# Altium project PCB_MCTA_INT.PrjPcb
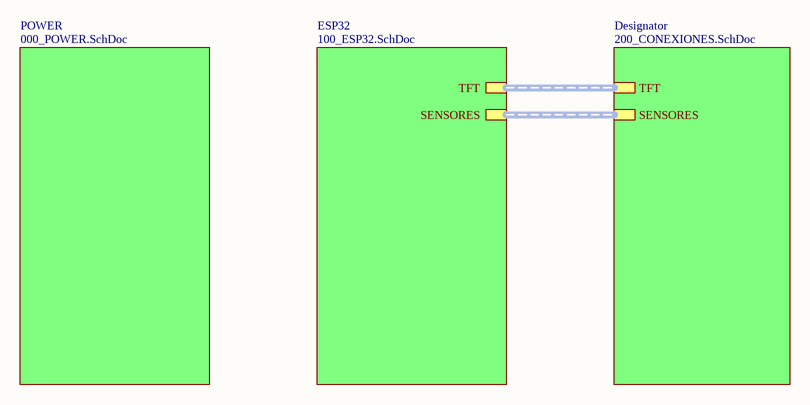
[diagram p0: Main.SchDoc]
4 sheets, 33 parts. Net scope: hierarchical (ports join the sheet entries above them; power ports are global).
Board file: PCB_MACETA.PcbDoc
Sheets:
  Main.SchDoc
    POWER = 000_POWER.SchDoc
    ESP32 = 100_ESP32.SchDoc
    Designator = 200_CONEXIONES.SchDoc

## Sheet Main.SchDoc: Maceta_Inteligente
size A4; DrawnBy: Alexis Andres Valencia; Revision: V1R1; SheetNumber: 1; SheetTotal: 4

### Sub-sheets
Designator = 200_CONEXIONES.SchDoc: TFT (harness TFT_HARNESS), SENSORES (harness SESORES_HARNESS)
ESP32 = 100_ESP32.SchDoc: TFT (harness TFT_HARNESS), SENSORES (harness SESORES_HARNESS)
POWER = 000_POWER.SchDoc: no entries

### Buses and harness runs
harness sheet Designator/SENSORES = sheet ESP32/SENSORES
harness sheet Designator/TFT = sheet ESP32/TFT

## Sheet 000_POWER.SchDoc: MACETA INTELIGENTE
size A4; DrawnBy: ALEXIS VALENCIA; SheetNumber: 2; SheetTotal: 4
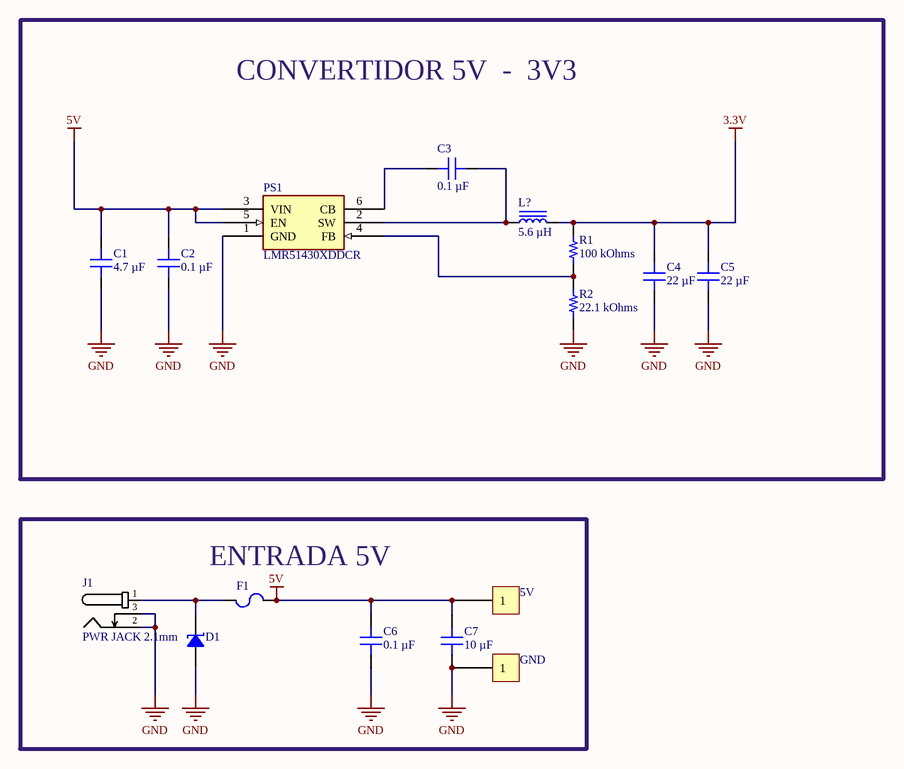
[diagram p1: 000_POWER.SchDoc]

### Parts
C1  4.7 µF  [CAP 0603_1608]
C2  0.1 µF  [CAP 0603_1608]
C3  0.1 µF  [CAP 0603_1608]
C4  22 µF  [CAP 0603_1608]
C5  22 µF  [CAP 0603_1608]
C6  0.1 µF  [CAP 0603_1608]
C7  10 µF  [CAP 0603_1608]
D1  SMAJ5.0A  [DO214AC SMA]  (value not drawn)
F1  MFU1206FF05000P100  [FUSE 1206_3216 0.6MM]  (value not drawn)
J1  PWR JACK 2.1mm  [CON_POWER_BARREL_2.1MM_3CONN]
L1  5.6 µH  [WURTH WE-PD 1280]
PS1  LMR51430XDDCR  [SOT95P280X110-6N]
R1  100 kOhms  [RES 0603_1608]
R2  22.1 kOhms  [RES 0603_1608]
TP1  5V  [Pad_SMD]
TP2  GND  [Pad_SMD]

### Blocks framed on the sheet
CONVERTIDOR 5V  -  3V3: C1-C5 L1 PS1 R1 R2
ENTRADA 5V: C6 C7 D1 F1 J1 TP1 TP2

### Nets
3.3V: C4.2 C5.2 L1.2 R1.2
5V: C1.2 C2.2 C6.2 C7.2 F1.2 PS1.3(VIN) PS1.5(EN) TP1.TP?(1)
GND: C1.1 C2.1 C4.1 C5.1 C6.1 C7.1 D1.1 J1.2 J1.3 PS1.1(GND) R2.1 TP2.TP?(1)
NetC3_1: C3.1 L1.1 PS1.2(SW)
NetC3_2: C3.2 PS1.6(CB)
NetD1_2: D1.2 F1.1 J1.1
NetPS1_4: PS1.4(FB) R1.1 R2.2

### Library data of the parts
C1 = 06033D475KAT2A: CAP CER 4.7UF 25V X5R 0603; manufacturer: KYOCERA AVX; Tolerance: ±10%
C2 C3 C6 = CL10E104KC8VPNC: CAP CER 100NF 100V X8L 0603; manufacturer: Samsung Electro-Mechanics; Tolerance: ±10%
C4 C5 = 0603YD226MAT2A: CAP CER 22UF 16V X5R 0603; manufacturer: KYOCERA AVX; Tolerance: ±20%
C7 = 0603X106M100CT: CAP CER 10UF 10V X5R 0603; manufacturer: Walsin Technology Corporation; Tolerance: ±20%
D1 = SMAJ5.0A: TVS DIODE 5VWM 9.2VC DO214AC; Manufacturer: Littelfuse Inc.; Current - Peak Pulse (10/1000µs): 43.5A; Power Line Protection: No; Power - Peak Pulse: 400W; Type: Zener; Unidirectional Channels: 1; Voltage - Breakdown (Min): 6.4V; Voltage - Clamping (Max) @ Ipp: 9.2V; Voltage - Reverse Standoff (Typ): 5V
F1 = MFU1206FF05000P100: FUSE BOARD MOUNT 5A 63VDC 1206; Manufacturer: Vishay Beyschlag; Approval Agency: UL; Breaking Capacity @ Rated Voltage: 50A; Fuse Type: Board Mount (Cartridge Style Excluded); Melting I²t: 0.2275; Response Time: Fast Blow; Voltage Rating - DC: 63V
J1 = Con_Power_Jack_2.1mm_3pins: CONN PWR JACK 2X5.5MM SOLDER; Manufacturer: HCTL; Manufacturer Part Number: HC-DC-005-2.0T
L1 = 74477005: FIXED IND 5.6UH 8A 17 MOHM SMD; Manufacturer: Würth Elektronik; Current - Saturation: 8.2A; DC Resistance (DCR): 17mOhm Max; Frequency - Self Resonant: 24MHz; Inductance Frequency - Test: 1 kHz; Material - Core: Ferrite; Shielding: Shielded; Tolerance: -20%, +40%; Type: Drum Core, Wirewound
PS1 = LMR51430XDDCR: Power Supply; Manufacturer_Name: Texas Instruments
R1 = AA0603FR-07100KL: RES SMD 100K OHM 1% 1/10W 0603; Manufacturer: Yageo; Power (Watts): 0.1W, 1/10W; Temperature Coefficient: ±150ppm/°C
R2 = AC0603FR-0722K1L: RES SMD 22.1K OHM 1% 1/10W 0603; Manufacturer: Yageo; Power (Watts): 0.1W, 1/10W; Temperature Coefficient: ±100ppm/°C
TP1 TP2 = Test: Test1.5mm

## Sheet 100_ESP32.SchDoc: MACETA INTELIGENTE
size A4; DrawnBy: ALEXIS VALENCIA; SheetNumber: 3; SheetTotal: 4
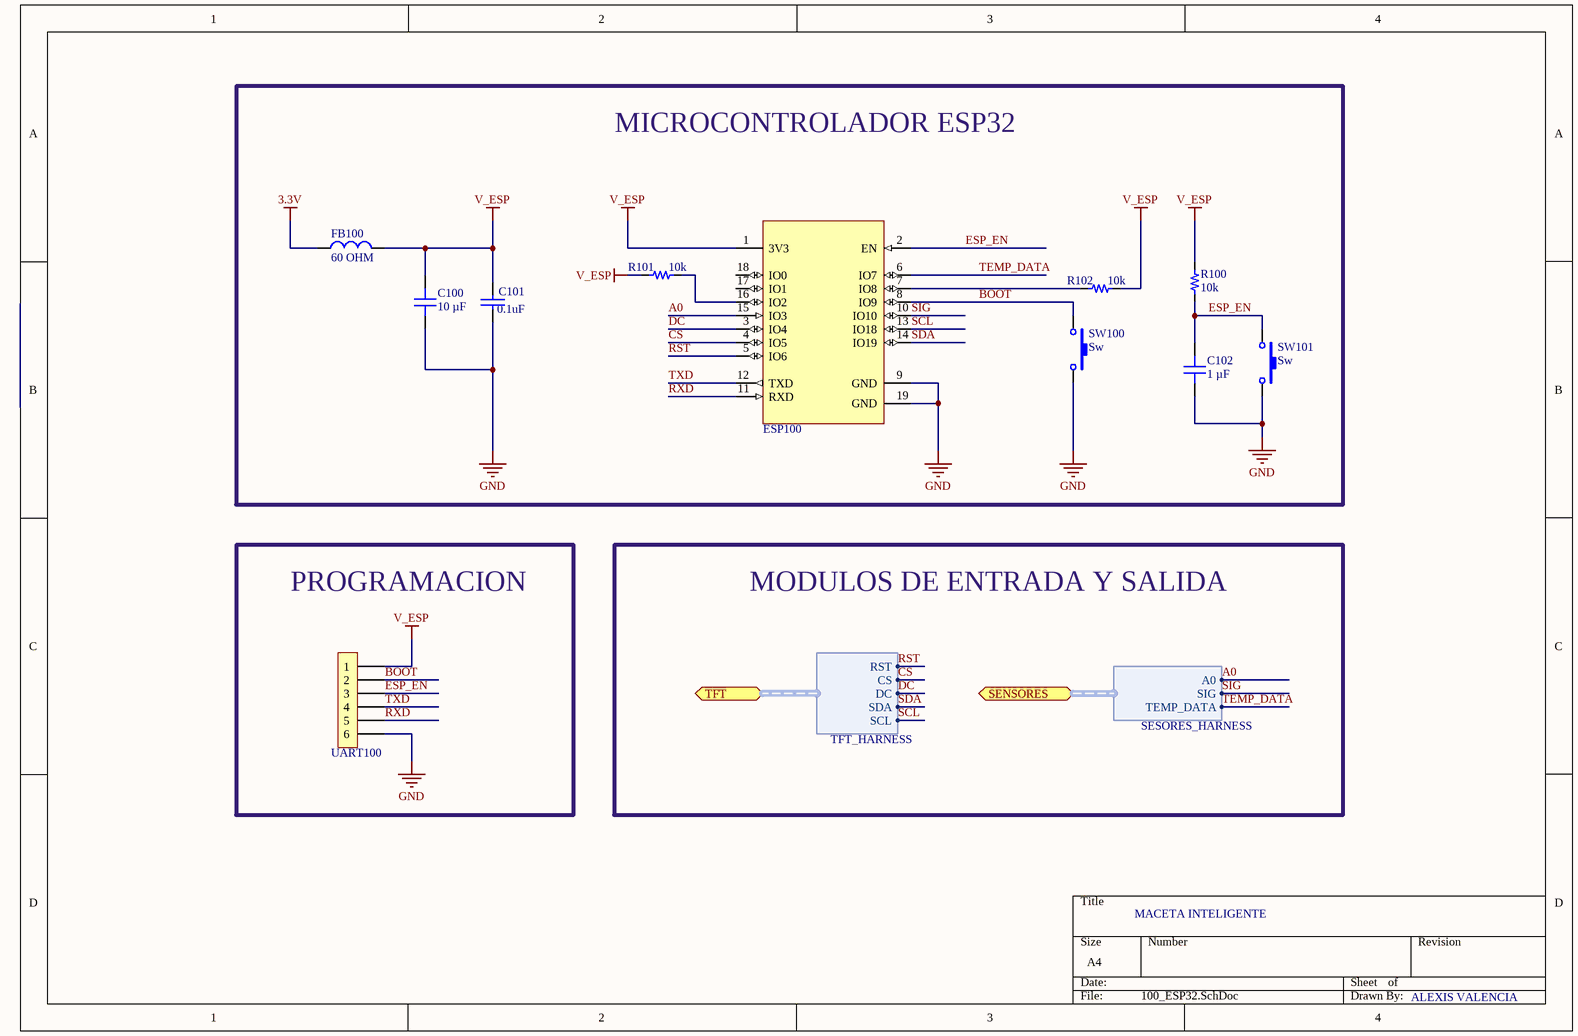
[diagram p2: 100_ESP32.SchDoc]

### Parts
C100  10 µF  [CAP 0603_1608]
C101  value 0.1uF  [0603_cap]  (hidden comment: 0.1uF 50V)
C102  1 µF  [CAP 0603_1608]
ESP100  ESP32-C3-WROOM-02-N4  [ESP32-C3-WROOM-02-N4]  (value not drawn)
FB100  value 60 OHM  [0603_fb]  (hidden comment: 60OHM 2A)
R100  value 10k  [0603_res]  (hidden comment: 10k 1/10W)
R101  value 10k  [0603_res]  (hidden comment: 10k 1/10W)
R102  value 10k  [0603_res]  (hidden comment: 10k 1/10W)
SW100  Sw  [Sw_PUSH_4.5x4.5x5mm]
SW101  Sw  [Sw_PUSH_4.5x4.5x5mm]
UART100  6x1  [H_6x1_TH_100mil]  (value not drawn)  (no BOM)

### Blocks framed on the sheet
MICROCONTROLADOR ESP32: C100-C102 ESP100 FB100 R100-R102 SW100 SW101
PROGRAMACION: UART100

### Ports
SENSORES (bidir, harness SESORES_HARNESS), TFT (bidir, harness TFT_HARNESS)

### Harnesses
TFT_HARNESS: RST, CS, DC, SDA, SCL
SESORES_HARNESS: A0, SIG, TEMP_DATA

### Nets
3.3V: FB100.1
GND: C100.1 C101.2 C102.1 ESP100.9(GND) ESP100.19(GND) SW100.2 SW101.2 UART100.6
V_ESP: C100.2 C101.1 ESP100.1(3V3) FB100.2 R100.2 R101.1 R102.2 UART100.1
A0: ESP100.15(IO3) ; port SENSORES.A0
BOOT: ESP100.8(IO9) SW100.1 UART100.2
CS: ESP100.4(IO5) ; port TFT.CS
DC: ESP100.3(IO4) ; port TFT.DC
ESP_EN: C102.2 ESP100.2(EN) R100.1 SW101.1 UART100.3
RST: ESP100.5(IO6) ; port TFT.RST
RXD: ESP100.11(RXD) UART100.5
SCL: ESP100.13(IO18) ; port TFT.SCL
SDA: ESP100.14(IO19) ; port TFT.SDA
SIG: ESP100.10(IO10) ; port SENSORES.SIG
TEMP_DATA: ESP100.6(IO7) ; port SENSORES.TEMP_DATA
TXD: ESP100.12(TXD) UART100.4
NetESP100_7: ESP100.7(IO8) R102.1
NetESP100_16: ESP100.16(IO2) R101.2

Not connected (* = marked no-connect by the designer): ESP100 17(IO1) 18(IO0)

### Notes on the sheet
- MODULOS DE ENTRADA Y SALIDA

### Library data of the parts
C100 = 06033D106KAT2A: CAP CER 10UF 25V X5R 0603; manufacturer: KYOCERA AVX; Tolerance: ±10%
C101 = Cap_0.1uF_0603_50V: 50V 100nF Y5V -20%~+80% 0603 Multilayer Ceramic Capacitors MLCC - SMD/SMT ROHS; Manufacturer: Walsin Tech Corp; Manufacturer Part Number: 0603F104Z500CT
C102 = 0603B105K250CT: CAP CER 1UF 25V X7R 0603; manufacturer: Walsin Technology Corporation; Tolerance: ±10%
ESP100 = MCU_ESP32-C3-WROOM-02-N4: RF TXRX MOD BT WIFI PCB TH SMD; Manufacturer: Espressif Systems
FB100 = FB_60_0603_2A: 2A 1 100mΩ 60Ω@100MHz ±25% 0603 Ferrite Beads ROHS; Manufacturer: TAI-TECH; Manufacturer Part Number: HCB1608KF-600T20
R100-R102 = Res_10k_0603_1/10W: RES SMD 10k OHM 5% 1/10W 0603; Manufacturer: FOJAN; Manufacturer Part Number: FRC0603J103TS
SW100 SW101 = Sw_PUSH_4.5x4.5x5.0xmm: SWITCH TACTILE SPST-NO 0.05A 12V; Manufacturer: BZCN; Manufacturer Part Number: TSC015A05026A
UART100 = H_Male_6x1_TH_100mil

## Sheet 200_CONEXIONES.SchDoc: MACETA INTELIGENTE
size A4; DrawnBy: ALEXIS VALENCIA; SheetNumber: 4; SheetTotal: 4
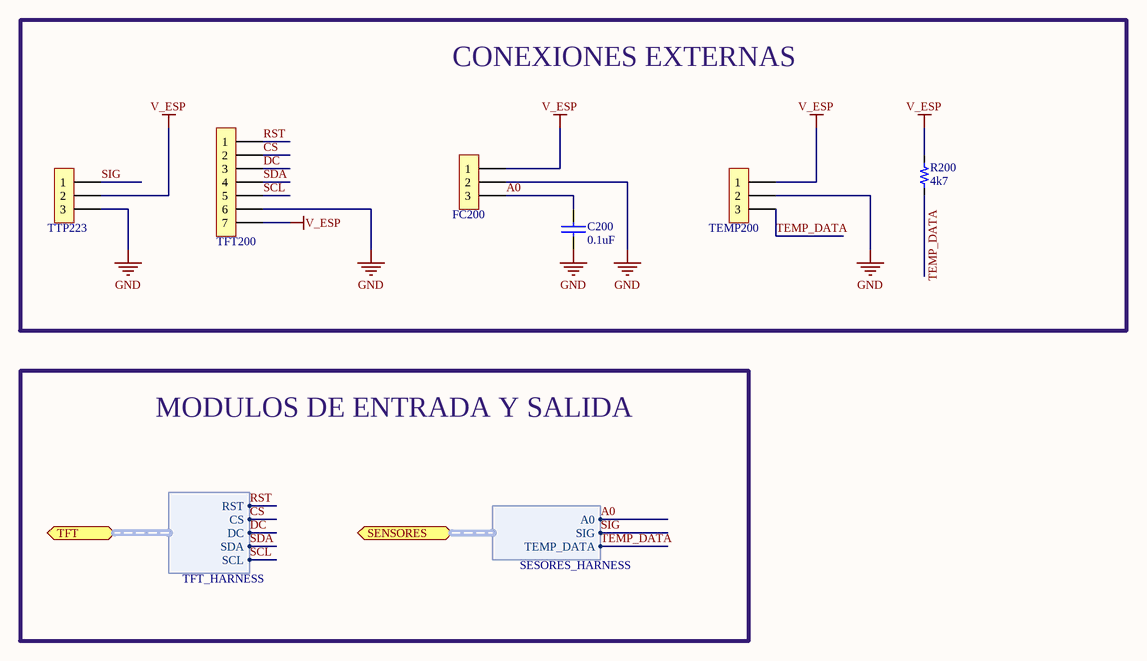
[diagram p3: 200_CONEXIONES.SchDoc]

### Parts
C200  value 0.1uF  [0603_cap]  (hidden comment: 0.1uF 50V)
FC200  3x1  [H_3X1_TH_100mil]  (value not drawn)  (no BOM)
R200  value 4k7  [0603_res]  (hidden comment: 4k7 1/10W)
TEMP200  3x1  [H_3X1_TH_100mil]  (value not drawn)  (no BOM)
TFT200  7x1  [H_7x1_TH_100mil]  (value not drawn)  (no BOM)
TTP223  3x1  [H_3X1_TH_100mil]  (value not drawn)  (no BOM)

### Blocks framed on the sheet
CONEXIONES EXTERNAS: C200 FC200 R200 TEMP200 TFT200 TTP223

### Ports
SENSORES (bidir, harness SESORES_HARNESS), TFT (bidir, harness TFT_HARNESS)

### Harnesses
TFT_HARNESS: RST, CS, DC, SDA, SCL
SESORES_HARNESS: A0, SIG, TEMP_DATA

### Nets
GND: C200.2 FC200.2 TEMP200.2 TFT200.6 TTP223.3
V_ESP: FC200.1 R200.1 TEMP200.1 TFT200.7 TTP223.2
A0: C200.1 FC200.3 ; port SENSORES.A0
CS: TFT200.2 ; port TFT.CS
DC: TFT200.3 ; port TFT.DC
RST: TFT200.1 ; port TFT.RST
SCL: TFT200.5 ; port TFT.SCL
SDA: TFT200.4 ; port TFT.SDA
SIG: TTP223.1 ; port SENSORES.SIG
TEMP_DATA: R200.2 TEMP200.3 ; port SENSORES.TEMP_DATA

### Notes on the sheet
- MODULOS DE ENTRADA Y SALIDA

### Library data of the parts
C200 = Cap_0.1uF_0603_50V: as C101 on sheet 100_ESP32
FC200 TEMP200 TTP223 = H_Male_3x1_TH_100mil
R200 = Res_4k7_0603_1/10W: 100mW Thick Film Resistor 75V ±1% 4.7kΩ 0603 Chip Resistor - Surface Mount ROHS; Manufacturer: VO; Manufacturer Part Number: SCR0603F4K7
TFT200 = H_Male_7x1_TH_100mil

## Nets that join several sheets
3.3V: 000_POWER (C4.2 C5.2 L1.2 R1.2), 100_ESP32 (FB100.1)
GND: 000_POWER (12 pins), 100_ESP32 (8 pins), 200_CONEXIONES (5 pins)
V_ESP: 100_ESP32 (8 pins), 200_CONEXIONES (5 pins)
A0: 100_ESP32 (ESP100.15), 200_CONEXIONES (C200.1 FC200.3)
CS: 100_ESP32 (ESP100.4), 200_CONEXIONES (TFT200.2)
DC: 100_ESP32 (ESP100.3), 200_CONEXIONES (TFT200.3)
RST: 100_ESP32 (ESP100.5), 200_CONEXIONES (TFT200.1)
SCL: 100_ESP32 (ESP100.13), 200_CONEXIONES (TFT200.5)
SDA: 100_ESP32 (ESP100.14), 200_CONEXIONES (TFT200.4)
SIG: 100_ESP32 (ESP100.10), 200_CONEXIONES (TTP223.1)
TEMP_DATA: 100_ESP32 (ESP100.6), 200_CONEXIONES (R200.2 TEMP200.3)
